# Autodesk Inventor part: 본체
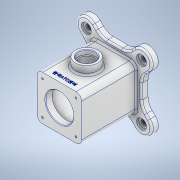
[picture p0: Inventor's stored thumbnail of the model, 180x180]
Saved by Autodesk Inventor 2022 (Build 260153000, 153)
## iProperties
Created: 2022-05
Part Number: 본체
Material: 알루미늄 6061
Document SubType Name: Modeling
Designer: Admin
Mass: 1072.55 g
Surface Area: 894.235 cm^2
Volume: 397.242 cm^3
Density: 2.7 g/cm^3
Appearance: 알루미늄 - 평지
Author: Admin
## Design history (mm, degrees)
sketch "스케치1"
  geometry: L1 (0, -56)-(0, 56) reference; L2 (-56, 0)-(56, 0) reference; L3 (-40, 40)-(40, 40); L4 (40, 40)-(40, -40); L5 (40, -40)-(-40, -40); L6 (-40, -40)-(-40, 40); L7 (-40, 40)-(40, -40); L8 (40, 40)-(-40, -40); 1 further point
  constraints: 12 end point, 2 midpoint, 2 parallel, 1 horizontal, 1 perpendicular
  dimensions: "d0" = 80 distance of L3.end L4.end; "d1" = 80 distance of L3.start L3.end
extrude "돌출1" new body sketch "스케치1" stored distance "d2" = 110; taper "d3" = 0 deg
sketch "스케치2"
  geometry: L1 (49, 49)-(-49, 49); L2 (-49, 49)-(-49, -49); L3 (-49, -49)-(49, -49); L4 (49, -49)-(49, 49); L5 (49, 49)-(-49, -49); L6 (-49, 49)-(49, -49); L7 (49.497, 49.497)-(-49.497, -49.497); L8 (36.77, 62.225)-(-62.225, -36.77); L9 (-36.77, -62.225)-(62.225, 36.77); L10 (-49.497, 49.497)-(49.497, -49.497); L11 (-62.225, 36.77)-(36.77, -62.225); L12 (62.225, -36.77)-(-36.77, 62.225); A1 r 18 centre (49.497, 49.497) between (62.225, 36.77) and (36.77, 62.225); A2 r 18 centre (-49.497, -49.497) between (-62.225, -36.77) and (-36.77, -62.225); A3 r 18 centre (-49.497, 49.497) between (-36.77, 62.225) and (-62.225, 36.77); A4 r 18 centre (49.497, -49.497) between (36.77, -62.225) and (62.225, -36.77); A5 r 70 centre (0, 0) between (49.497, 49.497) and (-49.497, 49.497); 13 further points
  constraints: 28 end point, 10 point on circle, 8 tangent, 6 midpoint, 5 centre point, 4 parallel, 3 coincident, 2 collinear, 1 horizontal, 1 perpendicular
  dimensions: "d4" = 98 distance of L2.end L3.end; "d5" = 98 distance of L3.end L1.start; "d6" = 36 distance between parallel lines of L8 L9; "d7" = 140 diameter of A5; "d9" = 36 distance between parallel lines of L11 L12
extrude "돌출2" join sketch "스케치2" distance "d10" = 12; taper "d11" = 0 deg
sketch "스케치3"
  geometry: L1 (-27.497, 98)-(3.23, 98) reference; C1 r 20 at (40, 49); 2 further points
  constraints: 1 centre point, 1 vertical alignment
  dimensions: "d12" = 49 distance from line of C1.centre L1; "d13" = 40 diameter of C1
extrude "돌출3" join sketch "스케치3" stored distance "d14" = 55; taper "d15" = 0 deg
sketch "스케치4"
  geometry: L1 (-94.496, 0)-(94.496, 0) reference; L2 (0, -77)-(0, 77) reference; L3 (40, 55)-(-40, 55) reference; L4 (25, 55)-(25, 43); L5 (25, 43)-(35, 43); L6 (35, 43)-(35, -43); L7 (35, -43)-(25, -43); L8 (25, -43)-(25, -55); L9 (-23.544, -55)-(23.544, -55) reference; L10 (25, 55)-(0, 55); L11 (0, 55)-(0, -55); L12 (0, -55)-(25, -55); L13 (23.544, -55)-(23.544, -43) reference; 2 further points
  constraints: 16 end point, 4 perpendicular, 4 point on line, 2 midpoint, 1 parallel
  dimensions: "d16" = 70 diameter of L6 L2; "d17" = 12 distance of L4.start L4.end; "d18" = 12 distance of L7.end L8.end; "d19" = 50 diameter of L4 L2
revolve "회전1" sketch "스케치4" stored, may be unused: angle "d20" = 90 deg
sketch "스케치5"
  geometry: C1 r 20 at (0, 0) reference; 2 further points
  constraints: 1 coincident
hole "구멍1" sketch "스케치5" at (0, 0) diameter "d21" = 25; stored, may be unused: countersink angle "d25" = 90 deg, drill point angle "d27" = 0 deg; dims "d22" = 6, "d23" = 30, "d24" = 8, "d26" = 8
sketch "스케치6"
  geometry: A1 r 18 centre (-49.497, 49.497) between (-36.77, 62.225) and (-62.225, 36.77) reference; A2 r 18 centre (49.497, 49.497) between (62.225, 36.77) and (36.77, 62.225) reference; A3 r 18 centre (49.497, -49.497) between (36.77, -62.225) and (62.225, -36.77) reference; A4 r 18 centre (-49.497, -49.497) between (-62.225, -36.77) and (-36.77, -62.225) reference; 5 further points
  constraints: 4 coincident
hole "구멍2" sketch "스케치6" at (-49.497, 49.497), (49.497, 49.497), (49.497, -49.497), (-49.497, -49.497) diameter "d28" = 10; stored, may be unused: countersink angle "d32" = 90 deg, drill point angle "d34" = 0 deg; dims "d29" = 6, "d30" = 18, "d31" = 4, "d33" = 8
fillet "모깎기1" dims "d35" = 10
sketch "스케치7"
  geometry: L1 (-30, -40)-(30, -40) reference; L2 (40, -30)-(40, 30) reference; L3 (30, 40)-(-30, 40) reference; L4 (-40, 30)-(-40, -30) reference; C1 r 25 at (0, 0) reference; A1 r 10 centre (-30, -30) between (-40, -30) and (-30, -40) reference; A2 r 10 centre (30, -30) between (30, -40) and (40, -30) reference; A3 r 10 centre (30, 30) between (40, 30) and (30, 40) reference; A4 r 10 centre (-30, 30) between (-30, 40) and (-40, 30) reference; 5 further points
  constraints: 4 coincident
hole "구멍3" sketch "스케치7" at (-30, 30), (30, 30), (30, -30), (-30, -30) diameter "d36" = 3.242; stored, may be unused: countersink angle "d40" = 90 deg, drill point angle "d42" = 118 deg; dims "d37" = 8, "d38" = 18, "d39" = 4, "d41" = 10
fillet "모깎기2" dims "d43" = 25
fillet "모깎기3" dims "d44" = 3
chamfer "모따기1" distance "d45" = 1; stored, may be unused: second distance "d46" = 2, angle "d47" = 45 deg
sketch "스케치8"
  geometry: L1 (60, 0)-(0, 0) reference; 2 further points
  constraints: 1 vertical alignment, 1 other
  dimensions: "d48" = 10 distance from line of L1 point (30, 10)
feature "엠보싱1" sketch "스케치8" dims "d0" = 80, "d1" = 80, "d4" = 98, "d5" = 98, "d6" = 36, "d7" = 140, "d9" = 36, "d49" = 0.5, "d50" = 0
sketch "스케치9"
  geometry: L1 (0, -94.496)-(0, 94.496) reference; L2 (94.496, 0)-(-94.496, 0) reference; 5 further points
  constraints: 4 symmetric about line
  dimensions: "d51" = 60 distance of point (-30, -30) point (30, -30); "d59" = 60 distance of point (30, -30) point (30, 30)
hole "구멍4" sketch "스케치9" at (30, 30), (30, -30), (-30, -30), (-30, 30) diameter "d52" = 3.242; stored, may be unused: countersink angle "d56" = 90 deg, drill point angle "d58" = 118 deg; dims "d53" = 8, "d54" = 4, "d55" = 2, "d57" = 10
node "솔리드1"
node "투영된 루프1"
feature "A9D066F2-1C7D-4E18-AEED-F7BC21143FA4" dims "d28" = 10, "d29" = 6, "d30" = 18, "d31" = 4, "d32" = 90 deg, "d33" = 8, "d34" = 0
